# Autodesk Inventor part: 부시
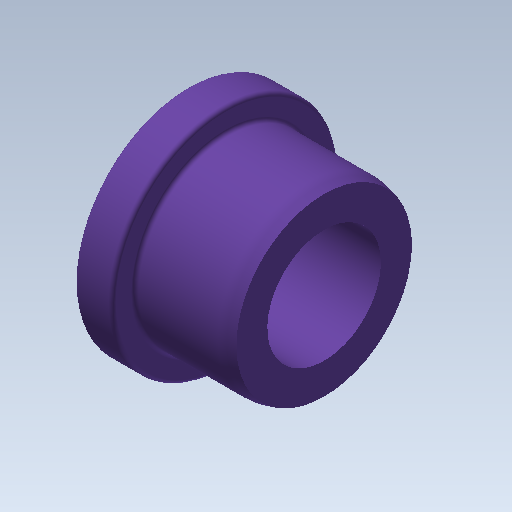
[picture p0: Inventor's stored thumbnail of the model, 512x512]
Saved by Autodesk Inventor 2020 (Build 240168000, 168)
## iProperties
Created: 2016-05
Part Number: 부시
Document SubType Name: Modeling
Designer: mduedu
Density: 7.86 g/cm^3
Material: 강철, 연강
Appearance: 보라색
Author: mduedu
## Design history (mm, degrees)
sketch "스케치1"
  geometry: L1 (0, 0)-(18, 0); L2 (1.5, 7.5)-(18, 7.5); L3 (18, 7.5)-(18, 11.598); L4 (16.5, 12)-(5, 12); L5 (5, 12)-(5, 15); L6 (5, 15)-(0, 15); L7 (0, 15)-(0, 7.902); L8 (0, 7.902)-(1.5, 7.5); L9 (16.5, 12)-(18, 11.598)
  constraints: 18 end point, 4 parallel, 1 horizontal, 1 perpendicular, 1 point on line, 1 vertical, 1 vertical alignment
  dimensions: "d0" = 18 distance of L1.start L1.end; "d1" = 15 diameter of L2 L1; "d2" = 24 diameter of L4 L1; "d3" = 5 distance of L5.end L6.end; "d4" = 30 diameter of L6 L1; "d9" = 15 deg angle of L2 L8; "d10" = 1.5 horizontal distance of L7.end L2.start; "d13" = 15 deg angle of L4 L9; "d14" = 1.5 distance from line of L4.start L3
revolve "회전1" sketch "스케치1" stored, may be unused: angle "d5" = 90 deg
fillet "모깎기1" dims "d11" = 4
fillet "모깎기2" dims "d12" = 0.5
node "솔리드1"
